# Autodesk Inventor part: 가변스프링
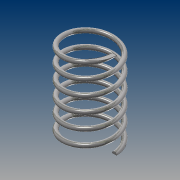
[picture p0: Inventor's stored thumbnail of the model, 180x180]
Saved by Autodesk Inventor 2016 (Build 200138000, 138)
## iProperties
Created: 2016-06
Part Number: 가변스프링
Material: 스테인레스 스틸
Document SubType Name: Modeling
Designer: sys
Density: 8 g/cm^3
Appearance: 반연마
Mass: 84.3547 g
Surface Area: 106.584 cm^2
Volume: 10.5443 cm^3
Author: sys
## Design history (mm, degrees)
sketch "스케치1"
  geometry: L1 (0, 0)-(-22.5, 0); L2 (-22.5, 0)-(-22.5, 80); L3 (-22.5, 80)-(0, 80); L4 (0, 80)-(0, 0); C1 r 2 at (-22.5, 0)
  constraints: 8 end point, 2 parallel, 1 centre point, 1 coincident, 1 horizontal, 1 perpendicular
  dimensions: "d0" = 80 distance between parallel lines of L1 L3 (derived); "d1" = 45 diameter of L2 L4; "d2" = 4 diameter of C1
feature "코일1" sketch "스케치1" pitch "d3" = 10; turns "d5" = 6; dims "d4" = 80 (= d0), "d6" = 0, angle "d7" = 90 deg, angle "d8" = 90 deg, "d9" = 0, "d10" = 0
sketch "스케치2"
  geometry: L1 (24.5, 0)-(20.5, 0) reference; L2 (24.5, 0)-(20.5, 0) reference; 1 further point
  constraints: 2 horizontal alignment
extrude "돌출1" cut sketch "스케치2" stored distance "d11" = 10; taper "d12" = 0 deg
node "작업 평면1"
sketch "스케치3"
  geometry: L1 (20.5, 0)-(24.5, 0) reference; 1 further point
  constraints: 1 horizontal alignment
extrude "돌출2" cut sketch "스케치3" stored distance "d14" = 10; taper "d15" = 0 deg
node "솔리드1"
node "절단 모서리 투영1"
node "절단 모서리 투영2"
node "절단 모서리 투영3"
